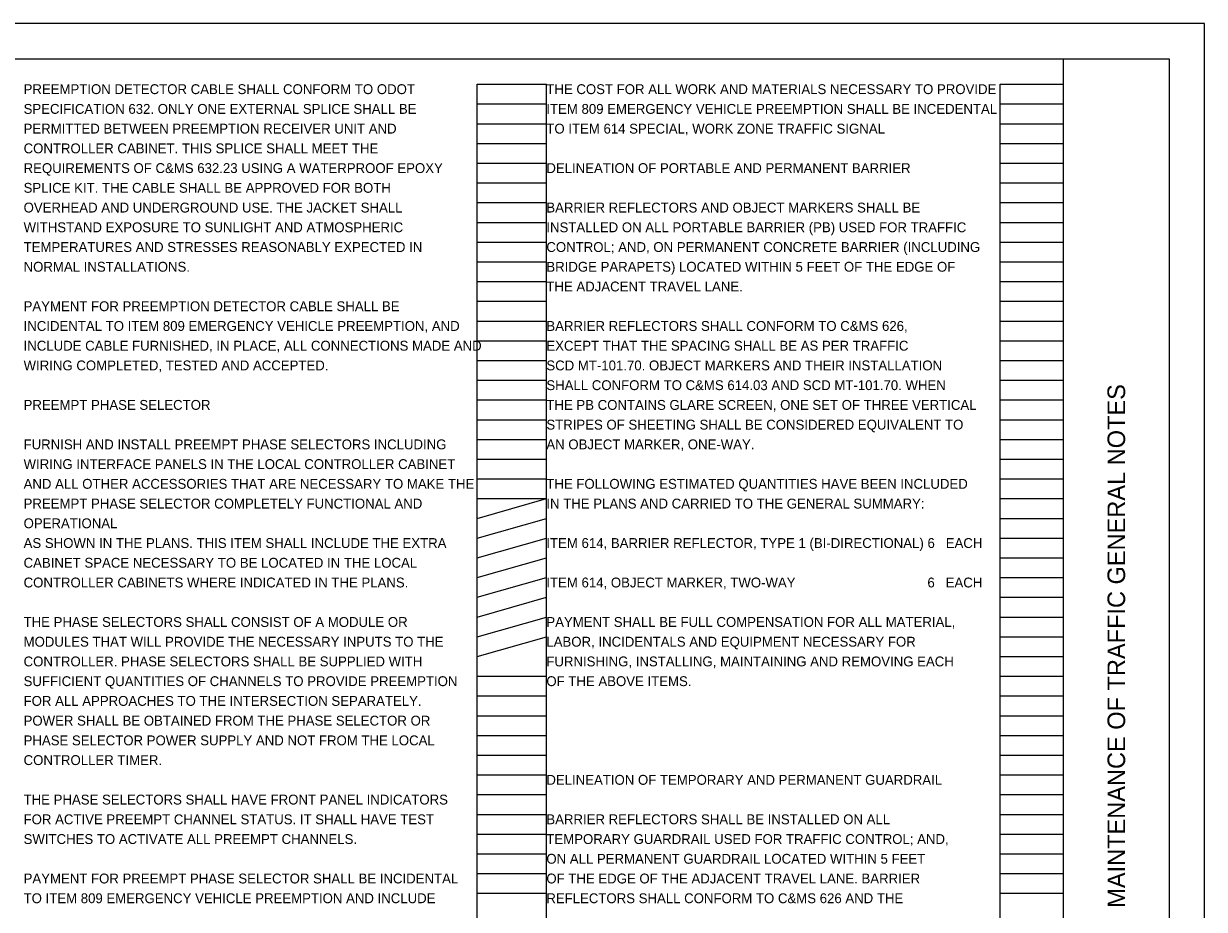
# Model space of a CAD drawing. Extents: x 0 to 34, y 0 to 22.
# Drawn here: x 17.24 to 34, y 9.43 to 22 of the extents above; entities that cross this region are included whole.
import ezdxf

# ---------------------------------------------------------------- set-up
doc = ezdxf.new("R2010")
doc.units = 0
for name, color, linetype in [('SH_Border', 7, 'Continuous'), ('SH_Cut_Line', 7, 'Continuous'), ('SH_Data', 7, 'Continuous'), ('SH_Text', 7, 'Continuous')]:
    doc.layers.add(name, color=color, linetype=linetype)

msp = doc.modelspace()

# ---------------------------------------------------------------- linework, layer by layer
at = {"layer": 'SH_Border'}
msp.add_line((32, 0.5), (32, 21.5), dxfattribs=at)
msp.add_lwpolyline([(1.5, 21.5), (33.5, 21.5), (33.5, 0.5), (1.5, 0.5)], close=True, dxfattribs=at)
at = {"layer": 'SH_Cut_Line'}
msp.add_lwpolyline([(0, 0), (34, 0), (34, 22), (0, 22)], close=True, dxfattribs=at)
at = {"layer": 'SH_Data'}
for p, q in [((23.68, 0.98), (23.68, 21.14)), ((23.68, 21.14), (24.66, 21.14)), ((24.66, 0.98), (24.66, 21.14)), ((31.1, 0.98), (31.1, 21.14)), ((31.1, 21.14), (32, 21.14)), ((32, 0.98), (32, 21.14)), ((23.68, 20.86), (24.66, 20.86)), ((31.1, 20.86), (32, 20.86)), ((23.68, 20.58), (24.66, 20.58)), ((31.1, 20.58), (32, 20.58)), ((23.68, 20.3), (24.66, 20.3)), ((31.1, 20.3), (32, 20.3)), ((23.68, 20.02), (24.66, 20.02)), ((31.1, 20.02), (32, 20.02)), ((23.68, 19.74), (24.66, 19.74)), ((31.1, 19.74), (32, 19.74)), ((23.68, 19.46), (24.66, 19.46)), ((31.1, 19.46), (32, 19.46)), ((23.68, 19.18), (24.66, 19.18)), ((31.1, 19.18), (32, 19.18)), ((23.68, 18.9), (24.66, 18.9)), ((31.1, 18.9), (32, 18.9)), ((23.68, 18.62), (24.66, 18.62)), ((31.1, 18.62), (32, 18.62)), ((23.68, 18.34), (24.66, 18.34)), ((31.1, 18.34), (32, 18.34)), ((23.68, 18.06), (24.66, 18.06)), ((31.1, 18.06), (32, 18.06)), ((23.68, 17.78), (24.66, 17.78)), ((31.1, 17.78), (32, 17.78)), ((23.68, 17.5), (24.66, 17.5)), ((31.1, 17.5), (32, 17.5)), ((23.68, 17.22), (24.66, 17.22)), ((31.1, 17.22), (32, 17.22)), ((23.68, 16.94), (24.66, 16.94)), ((31.1, 16.94), (32, 16.94)), ((23.68, 16.66), (24.66, 16.66)), ((31.1, 16.66), (32, 16.66)), ((23.68, 16.38), (24.66, 16.38)), ((31.1, 16.38), (32, 16.38)), ((23.68, 16.1), (24.66, 16.1)), ((31.1, 16.1), (32, 16.1)), ((23.68, 15.82), (24.66, 15.82)), ((31.1, 15.82), (32, 15.82)), ((23.68, 15.54), (24.66, 15.54)), ((31.1, 15.54), (32, 15.54)), ((23.68, 15.26), (24.66, 15.26)), ((23.68, 14.98), (24.66, 15.26)), ((31.1, 15.26), (32, 15.26)), ((23.68, 14.7), (24.66, 14.98)), ((31.1, 14.98), (32, 14.98)), ((23.68, 14.42), (24.66, 14.7)), ((31.1, 14.7), (32, 14.7)), ((23.68, 14.14), (24.66, 14.42)), ((31.1, 14.42), (32, 14.42)), ((23.68, 13.86), (24.66, 14.14)), ((31.1, 14.14), (32, 14.14)), ((23.68, 13.58), (24.66, 13.86)), ((31.1, 13.86), (32, 13.86)), ((23.68, 13.3), (24.66, 13.58)), ((31.1, 13.58), (32, 13.58)), ((23.68, 13.02), (24.66, 13.3)), ((31.1, 13.3), (32, 13.3)), ((31.1, 13.02), (32, 13.02)), ((23.68, 12.74), (24.66, 12.74)), ((31.1, 12.74), (32, 12.74)), ((23.68, 12.46), (24.66, 12.46)), ((31.1, 12.46), (32, 12.46)), ((23.68, 12.18), (24.66, 12.18)), ((31.1, 12.18), (32, 12.18)), ((23.68, 11.9), (24.66, 11.9)), ((31.1, 11.9), (32, 11.9)), ((23.68, 11.62), (24.66, 11.62)), ((31.1, 11.62), (32, 11.62)), ((23.68, 11.34), (24.66, 11.34)), ((31.1, 11.34), (32, 11.34)), ((23.68, 11.06), (24.66, 11.06)), ((31.1, 11.06), (32, 11.06)), ((23.68, 10.78), (24.66, 10.78)), ((31.1, 10.78), (32, 10.78)), ((23.68, 10.5), (24.66, 10.5)), ((31.1, 10.5), (32, 10.5)), ((23.68, 10.22), (24.66, 10.22)), ((31.1, 10.22), (32, 10.22)), ((23.68, 9.94), (24.66, 9.94)), ((31.1, 9.94), (32, 9.94)), ((23.68, 9.66), (24.66, 9.66)), ((31.1, 9.66), (32, 9.66))]:
    msp.add_line(p, q, dxfattribs=at)

# ---------------------------------------------------------------- texts
msp.add_text('MAINTENANCE OF TRAFFIC GENERAL NOTES', height=0.25, rotation=90, dxfattribs=at).set_placement((32.875, 9.455))
at = {"layer": 'SH_Text'}
for s, p in [('PREEMPTION DETECTOR CABLE SHALL CONFORM TO ODOT', (17.24, 21)), ('THE COST FOR ALL WORK AND MATERIALS NECESSARY TO PROVIDE ', (24.66, 21)), ('SPECIFICATION 632. ONLY ONE EXTERNAL SPLICE SHALL BE', (17.24, 20.72)), ('ITEM 809 EMERGENCY VEHICLE PREEMPTION SHALL BE INCEDENTAL ', (24.66, 20.72)), ('PERMITTED BETWEEN PREEMPTION RECEIVER UNIT AND', (17.24, 20.44)), ('TO ITEM 614 SPECIAL, WORK ZONE TRAFFIC SIGNAL', (24.66, 20.44)), ('CONTROLLER CABINET. THIS SPLICE SHALL MEET THE', (17.24, 20.16)), ('REQUIREMENTS OF C&MS 632.23 USING A WATERPROOF EPOXY', (17.24, 19.88)), ('DELINEATION OF PORTABLE AND PERMANENT BARRIER', (24.66, 19.88)), ('SPLICE KIT. THE CABLE SHALL BE APPROVED FOR BOTH', (17.24, 19.6)), ('OVERHEAD AND UNDERGROUND USE. THE JACKET SHALL', (17.24, 19.32)), ('BARRIER REFLECTORS AND OBJECT MARKERS SHALL BE', (24.66, 19.32)), ('WITHSTAND EXPOSURE TO SUNLIGHT AND ATMOSPHERIC', (17.24, 19.04)), ('INSTALLED ON ALL PORTABLE BARRIER (PB) USED FOR TRAFFIC', (24.66, 19.04)), ('TEMPERATURES AND STRESSES REASONABLY EXPECTED IN', (17.24, 18.76)), ('CONTROL; AND, ON PERMANENT CONCRETE BARRIER (INCLUDING', (24.66, 18.76)), ('NORMAL INSTALLATIONS.', (17.24, 18.48)), ('BRIDGE PARAPETS) LOCATED WITHIN 5 FEET OF THE EDGE OF', (24.66, 18.48)), ('THE ADJACENT TRAVEL LANE.', (24.66, 18.2)), ('PAYMENT FOR PREEMPTION DETECTOR CABLE SHALL BE ', (17.24, 17.92)), ('INCIDENTAL TO ITEM 809 EMERGENCY VEHICLE PREEMPTION, AND', (17.24, 17.64)), ('BARRIER REFLECTORS SHALL CONFORM TO C&MS 626,', (24.66, 17.64)), ('INCLUDE CABLE FURNISHED, IN PLACE, ALL CONNECTIONS MADE AND', (17.24, 17.36)), ('EXCEPT THAT THE SPACING SHALL BE AS PER TRAFFIC', (24.66, 17.36)), ('WIRING COMPLETED, TESTED AND ACCEPTED.', (17.24, 17.08)), ('SCD MT-101.70. OBJECT MARKERS AND THEIR INSTALLATION', (24.66, 17.08)), ('SHALL CONFORM TO C&MS 614.03 AND SCD MT-101.70. WHEN', (24.66, 16.8)), ('PREEMPT PHASE SELECTOR', (17.24, 16.52)), ('THE PB CONTAINS GLARE SCREEN, ONE SET OF THREE VERTICAL', (24.66, 16.52)), ('STRIPES OF SHEETING SHALL BE CONSIDERED EQUIVALENT TO', (24.66, 16.24)), ('FURNISH AND INSTALL PREEMPT PHASE SELECTORS INCLUDING ', (17.24, 15.96)), ('AN OBJECT MARKER, ONE-WAY.', (24.66, 15.96)), ('WIRING INTERFACE PANELS IN THE LOCAL CONTROLLER CABINET ', (17.24, 15.68)), ('AND ALL OTHER ACCESSORIES THAT ARE NECESSARY TO MAKE THE ', (17.24, 15.4)), ('THE FOLLOWING ESTIMATED QUANTITIES HAVE BEEN INCLUDED', (24.66, 15.4)), ('PREEMPT PHASE SELECTOR COMPLETELY FUNCTIONAL AND ', (17.24, 15.12)), ('IN THE PLANS AND CARRIED TO THE GENERAL SUMMARY:', (24.66, 15.12)), ('OPERATIONAL', (17.24, 14.84)), ('AS SHOWN IN THE PLANS. THIS ITEM SHALL INCLUDE THE EXTRA', (17.24, 14.56)), ('ITEM 614, BARRIER REFLECTOR, TYPE 1 (BI-DIRECTIONAL)    ', (24.66, 14.56)), ('  6  ', (29.966, 14.56)), (' EACH', (30.277, 14.56)), ('CABINET SPACE NECESSARY TO BE LOCATED IN THE LOCAL', (17.24, 14.28)), ('CONTROLLER CABINETS WHERE INDICATED IN THE PLANS.', (17.24, 14)), ('ITEM 614, OBJECT MARKER, TWO-WAY                                     ', (24.66, 14)), ('  6  ', (29.965, 14)), (' EACH', (30.276, 14)), ('THE PHASE SELECTORS SHALL CONSIST OF A MODULE OR', (17.24, 13.44)), ('PAYMENT SHALL BE FULL COMPENSATION FOR ALL MATERIAL,', (24.66, 13.44)), ('MODULES THAT WILL PROVIDE THE NECESSARY INPUTS TO THE', (17.24, 13.16)), ('LABOR, INCIDENTALS AND EQUIPMENT NECESSARY FOR', (24.66, 13.16)), ('CONTROLLER. PHASE SELECTORS SHALL BE SUPPLIED WITH', (17.24, 12.88)), ('FURNISHING, INSTALLING, MAINTAINING AND REMOVING EACH', (24.66, 12.88)), ('SUFFICIENT QUANTITIES OF CHANNELS TO PROVIDE PREEMPTION', (17.24, 12.6)), ('OF THE ABOVE ITEMS.', (24.66, 12.6)), ('FOR ALL APPROACHES TO THE INTERSECTION SEPARATELY.', (17.24, 12.32)), ('POWER SHALL BE OBTAINED FROM THE PHASE SELECTOR OR', (17.24, 12.04)), ('PHASE SELECTOR POWER SUPPLY AND NOT FROM THE LOCAL', (17.24, 11.76)), ('CONTROLLER TIMER.', (17.24, 11.48)), ('DELINEATION OF TEMPORARY AND PERMANENT GUARDRAIL', (24.66, 11.2)), ('THE PHASE SELECTORS SHALL HAVE FRONT PANEL INDICATORS', (17.24, 10.92)), ('FOR ACTIVE PREEMPT CHANNEL STATUS. IT SHALL HAVE TEST', (17.24, 10.64)), ('BARRIER REFLECTORS SHALL BE INSTALLED ON ALL', (24.66, 10.64)), ('SWITCHES TO ACTIVATE ALL PREEMPT CHANNELS.', (17.24, 10.36)), ('TEMPORARY GUARDRAIL USED FOR TRAFFIC CONTROL; AND,', (24.66, 10.36)), ('ON ALL PERMANENT GUARDRAIL LOCATED WITHIN 5 FEET', (24.66, 10.08)), ('PAYMENT FOR PREEMPT PHASE SELECTOR SHALL BE INCIDENTAL', (17.24, 9.8)), ('OF THE EDGE OF THE ADJACENT TRAVEL LANE. BARRIER', (24.66, 9.8)), ('TO ITEM 809 EMERGENCY VEHICLE PREEMPTION AND INCLUDE', (17.24, 9.52)), ('REFLECTORS SHALL CONFORM TO C&MS 626 AND THE', (24.66, 9.52))]:
    msp.add_text(s, height=0.14, dxfattribs=at).set_placement(p)

doc.saveas('drawing.dxf')
